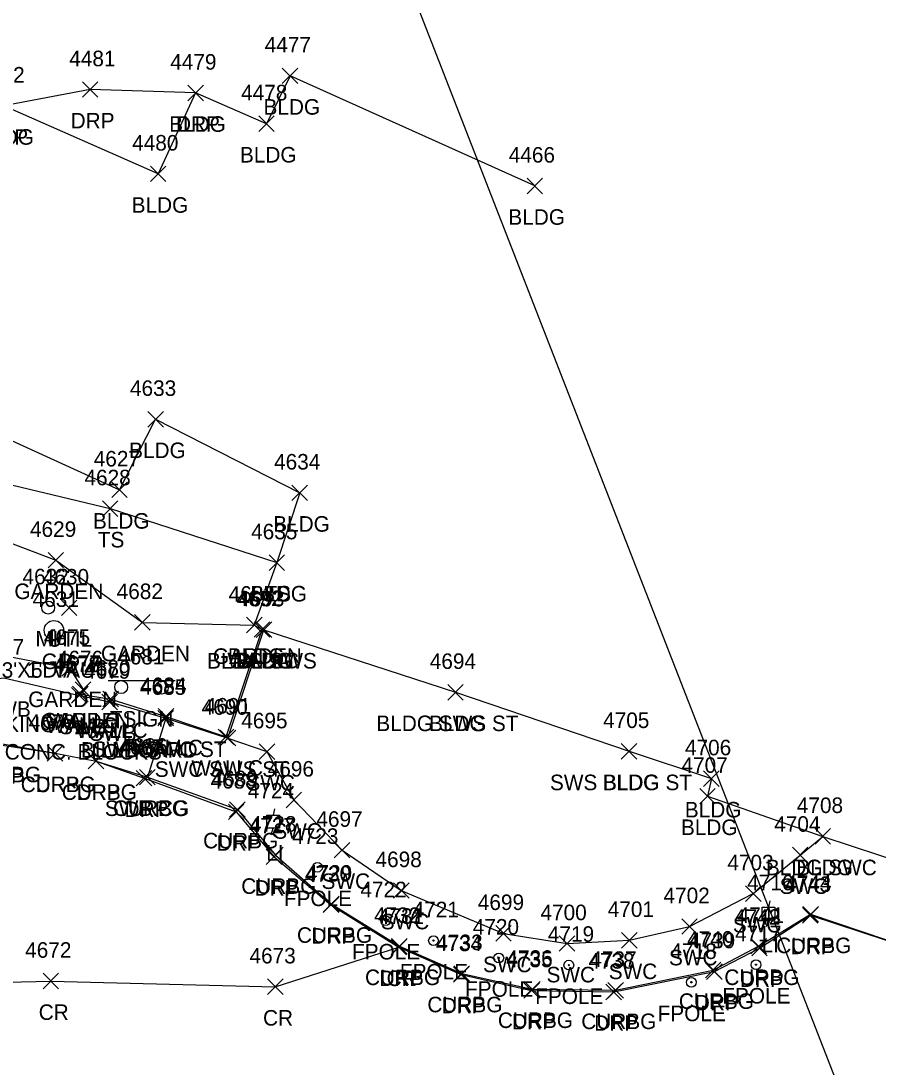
# Model space of a CAD drawing. Extents: x 49137 to 50946, y 9590 to 10709.
# Drawn here: x 50204 to 50314.2, y 10186.5 to 10321.1 of the extents above; entities that cross this region are included whole.
import ezdxf

# ---------------------------------------------------------------- set-up
doc = ezdxf.new("R2010")
doc.units = 0
for name, color, linetype in [('DCP', 7, 'Continuous'), ('L_A', 7, 'Continuous'), ('L_C', 7, 'Continuous'), ('L_I', 7, 'Continuous'), ('L_TIC', 7, 'Continuous'), ('LAPB', 7, 'Continuous'), ('LBC', 7, 'Continuous'), ('LELB', 7, 'Continuous'), ('LFP', 7, 'Continuous'), ('LW', 7, 'Continuous'), ('P_A', 7, 'Continuous'), ('P_I', 7, 'Continuous'), ('P_TIC', 7, 'Continuous'), ('PRC', 7, 'Continuous'), ('R_A', 7, 'Continuous'), ('R_I', 7, 'Continuous'), ('R_TIC', 7, 'Continuous'), ('RC', 7, 'Continuous'), ('RDP', 7, 'Continuous'), ('RGP', 7, 'Continuous'), ('RSW', 7, 'Continuous'), ('S_A', 7, 'Continuous'), ('S_C', 7, 'Continuous'), ('S_I', 7, 'Continuous'), ('SSGN', 7, 'Continuous'), ('U_A', 7, 'Continuous'), ('U_C', 7, 'Continuous'), ('U_I', 7, 'Continuous'), ('UDEFAULT', 7, 'Continuous'), ('ULP', 7, 'Continuous'), ('UUMH', 7, 'Continuous')]:
    doc.layers.add(name, color=color, linetype=linetype)

msp = doc.modelspace()

# ---------------------------------------------------------------- linework, layer by layer
at = {"layer": 'DCP'}
msp.add_lwpolyline([(49941.69, 9827.48), (50059.34, 9808.37), (50181.4, 9733.09), (50281.74, 9743.29), (50422.72, 9892.52), (50122.34, 10663.61), (50179.93, 10552.61), (50179.64, 10394.45), (50122.34, 10285.07), (50121.56, 10284.35)], dxfattribs=at)
at = {"layer": 'L_TIC'}
for points in [[(50237.6, 10313.07), (50239.6, 10315.07)], [(50239.6, 10313.07), (50237.6, 10315.07)], [(50225.45, 10310.86), (50227.45, 10312.86)], [(50227.45, 10310.86), (50225.45, 10312.86)], [(50234.57, 10306.91), (50236.57, 10308.91)], [(50236.57, 10306.91), (50234.57, 10308.91)], [(50220.64, 10300.45), (50222.64, 10302.45)], [(50222.64, 10300.45), (50220.64, 10302.45)], [(50269.1, 10298.9), (50271.1, 10300.9)], [(50271.1, 10298.9), (50269.1, 10300.9)], [(50220.31, 10268.88), (50222.31, 10270.88)], [(50222.31, 10268.88), (50220.31, 10270.88)], [(50215.66, 10259.8), (50217.66, 10261.8)], [(50217.66, 10259.8), (50215.66, 10261.8)], [(50238.85, 10259.41), (50240.85, 10261.41)], [(50240.85, 10259.41), (50238.85, 10261.41)], [(50214.46, 10257.38), (50216.46, 10259.38)], [(50216.46, 10257.38), (50214.46, 10259.38)], [(50207.47, 10250.74), (50209.47, 10252.74)], [(50209.47, 10250.74), (50207.47, 10252.74)], [(50235.9, 10250.43), (50237.9, 10252.43)], [(50237.9, 10250.43), (50235.9, 10252.43)], [(50235.9, 10250.43), (50237.9, 10252.43)], [(50237.9, 10250.43), (50235.9, 10252.43)], [(50218.61, 10242.74), (50220.61, 10244.74)], [(50220.61, 10242.74), (50218.61, 10244.74)], [(50233.01, 10242.4), (50235.01, 10244.4)], [(50235.01, 10242.4), (50233.01, 10244.4)], [(50233.01, 10242.4), (50235.01, 10244.4)], [(50235.01, 10242.4), (50233.01, 10244.4)], [(50234, 10241.83), (50236, 10243.83)], [(50236, 10241.83), (50234, 10243.83)], [(50234, 10241.83), (50236, 10243.83)], [(50236, 10241.83), (50234, 10243.83)], [(50234.24, 10241.8), (50236.24, 10243.8)], [(50236.24, 10241.8), (50234.24, 10243.8)], [(50209.25, 10236.84), (50211.25, 10238.84)], [(50211.25, 10236.84), (50209.25, 10238.84)], [(50210.97, 10234.09), (50212.97, 10236.09)], [(50212.97, 10234.09), (50210.97, 10236.09)], [(50210.97, 10234.09), (50212.97, 10236.09)], [(50212.97, 10234.09), (50210.97, 10236.09)], [(50258.89, 10233.75), (50260.89, 10235.75)], [(50260.89, 10233.75), (50258.89, 10235.75)], [(50210.63, 10233.52), (50212.63, 10235.52)], [(50212.63, 10233.52), (50210.63, 10235.52)], [(50214.53, 10232.88), (50216.53, 10234.88)], [(50216.53, 10232.88), (50214.53, 10234.88)], [(50221.64, 10230.64), (50223.64, 10232.64)], [(50223.64, 10230.64), (50221.64, 10232.64)], [(50229.37, 10228.01), (50231.37, 10230.01)], [(50231.37, 10228.01), (50229.37, 10230.01)], [(50281.22, 10226.15), (50283.22, 10228.15)], [(50283.22, 10226.15), (50281.22, 10228.15)], [(50291.8, 10222.64), (50293.8, 10224.64)], [(50293.8, 10222.64), (50291.8, 10224.64)], [(50291.3, 10220.38), (50293.3, 10222.38)], [(50293.3, 10220.38), (50291.3, 10222.38)], [(50306.14, 10215.21), (50308.14, 10217.21)], [(50308.14, 10215.21), (50306.14, 10217.21)]]:
    msp.add_lwpolyline(points, dxfattribs=at)
at = {"layer": 'LAPB'}
for points in [[(50157.96, 10267.97), (50152.3, 10249.84), (50148.96, 10238.47), (50151.49, 10231.52), (50159.69, 10232.28), (50178.06, 10237.47), (50196.39, 10240.52), (50210.25, 10237.84), (50211.97, 10235.09)], [(50157.96, 10267.97), (50167.36, 10269), (50188.37, 10259.39), (50208.47, 10251.74), (50219.61, 10243.74), (50234.01, 10243.4)]]:
    msp.add_lwpolyline(points, dxfattribs=at)
at = {"layer": 'LBC'}
for points in [[(50270.1, 10299.9), (50238.6, 10314.07), (50235.57, 10307.91), (50226.45, 10311.86), (50221.64, 10301.45), (50201.78, 10310.2), (50197.62, 10302.08), (50176.54, 10312.4), (50163.87, 10284.73), (50169.02, 10282.33), (50173.19, 10280.45), (50184.02, 10275.46), (50193.34, 10271.43), (50216.66, 10260.8), (50221.31, 10269.88), (50239.85, 10260.41), (50236.9, 10251.43), (50234.01, 10243.4), (50235, 10242.83), (50235.24, 10242.8), (50259.89, 10234.75)], [(50282.22, 10227.15), (50292.8, 10223.64), (50292.3, 10221.38), (50307.14, 10216.21), (50325.37, 10210.2), (50326.04, 10212.17), (50337.06, 10208.4)]]:
    msp.add_lwpolyline(points, dxfattribs=at)
at = {"layer": 'LELB'}
msp.add_lwpolyline([(50189.15, 10264.68), (50215.46, 10258.38), (50236.9, 10251.43)], dxfattribs=at)
at = {"layer": 'LFP'}
for centre, radius in [((50242.14, 10212.24), 0.625), ((50242.14, 10212.24), 0.0833), ((50250.91, 10205.37), 0.625), ((50250.91, 10205.37), 0.0833), ((50257.06, 10202.8), 0.625), ((50257.06, 10202.8), 0.0833), ((50265.46, 10200.57), 0.625), ((50265.46, 10200.57), 0.0833), ((50274.47, 10199.64), 0.625), ((50274.47, 10199.64), 0.0833), ((50298.54, 10199.7), 0.625), ((50298.54, 10199.7), 0.0833), ((50290.23, 10197.43), 0.625), ((50290.23, 10197.43), 0.0833)]:
    msp.add_circle(centre, radius, dxfattribs=at)
at = {"layer": 'LW'}
msp.add_lwpolyline([(50211.97, 10235.09), (50211.63, 10234.52), (50215.53, 10233.88), (50222.64, 10231.64), (50230.37, 10229.01), (50235, 10242.83)], dxfattribs=at)
at = {"layer": 'P_TIC'}
for points in [[(50251.6, 10200.95), (50253.6, 10202.95)], [(50253.6, 10200.95), (50251.6, 10202.95)], [(50206.83, 10196.59), (50208.83, 10198.59)], [(50208.83, 10196.59), (50206.83, 10198.59)], [(50235.7, 10195.86), (50237.7, 10197.86)], [(50237.7, 10195.86), (50235.7, 10197.86)]]:
    msp.add_lwpolyline(points, dxfattribs=at)
at = {"layer": 'PRC'}
msp.add_lwpolyline([(50141.03, 10194.61), (50160.28, 10196.49), (50207.83, 10197.59), (50236.7, 10196.86), (50252.6, 10201.95)], dxfattribs=at)
at = {"layer": 'R_TIC'}
for points in [[(50211.89, 10311.3), (50213.89, 10313.3)], [(50213.89, 10311.3), (50211.89, 10313.3)], [(50225.45, 10310.86), (50227.45, 10312.86)], [(50227.45, 10310.86), (50225.45, 10312.86)], [(50234.24, 10241.8), (50236.24, 10243.8)], [(50236.24, 10241.8), (50234.24, 10243.8)], [(50258.89, 10233.75), (50260.89, 10235.75)], [(50260.89, 10233.75), (50258.89, 10235.75)], [(50210.51, 10233.35), (50212.51, 10235.35)], [(50212.51, 10233.35), (50210.51, 10235.35)], [(50214.41, 10232.5), (50216.41, 10234.5)], [(50216.41, 10232.5), (50214.41, 10234.5)], [(50221.61, 10230.42), (50223.61, 10232.42)], [(50223.61, 10230.42), (50221.61, 10232.42)], [(50221.61, 10230.42), (50223.61, 10232.42)], [(50223.61, 10230.42), (50221.61, 10232.42)], [(50229.62, 10227.86), (50231.62, 10229.86)], [(50231.62, 10227.86), (50229.62, 10229.86)], [(50229.62, 10227.86), (50231.62, 10229.86)], [(50231.62, 10227.86), (50229.62, 10229.86)], [(50207.37, 10225.9), (50209.37, 10227.9)], [(50209.37, 10225.9), (50207.37, 10227.9)], [(50207.37, 10225.9), (50209.37, 10227.9)], [(50209.37, 10225.9), (50207.37, 10227.9)], [(50234.63, 10226.11), (50236.63, 10228.11)], [(50236.63, 10226.11), (50234.63, 10228.11)], [(50281.22, 10226.15), (50283.22, 10228.15)], [(50283.22, 10226.15), (50281.22, 10228.15)], [(50212.65, 10224.9), (50214.65, 10226.9)], [(50214.65, 10224.9), (50212.65, 10226.9)], [(50212.65, 10224.9), (50214.65, 10226.9)], [(50214.65, 10224.9), (50212.65, 10226.9)], [(50219.25, 10222.83), (50221.25, 10224.83)], [(50221.25, 10222.83), (50219.25, 10224.83)], [(50219.25, 10222.83), (50221.25, 10224.83)], [(50221.25, 10222.83), (50219.25, 10224.83)], [(50218.82, 10222.7), (50220.82, 10224.7)], [(50220.82, 10222.7), (50218.82, 10224.7)], [(50238.09, 10219.9), (50240.09, 10221.9)], [(50240.09, 10219.9), (50238.09, 10221.9)], [(50230.68, 10218.36), (50232.68, 10220.36)], [(50232.68, 10218.36), (50230.68, 10220.36)], [(50230.83, 10218.66), (50232.83, 10220.66)], [(50232.83, 10218.66), (50230.83, 10220.66)], [(50306.14, 10215.21), (50308.14, 10217.21)], [(50308.14, 10215.21), (50306.14, 10217.21)], [(50244.3, 10213.44), (50246.3, 10215.44)], [(50246.3, 10213.44), (50244.3, 10215.44)], [(50235.55, 10212.58), (50237.55, 10214.58)], [(50237.55, 10212.58), (50235.55, 10214.58)], [(50235.74, 10212.81), (50237.74, 10214.81)], [(50237.74, 10212.81), (50235.74, 10214.81)], [(50303.23, 10212.8), (50305.23, 10214.8)], [(50305.23, 10212.8), (50303.23, 10214.8)], [(50251.91, 10208.25), (50253.91, 10210.25)], [(50253.91, 10208.25), (50251.91, 10210.25)], [(50297.2, 10207.84), (50299.2, 10209.84)], [(50299.2, 10207.84), (50297.2, 10209.84)], [(50242.86, 10206.4), (50244.86, 10208.4)], [(50244.86, 10206.4), (50242.86, 10208.4)], [(50242.91, 10206.51), (50244.91, 10208.51)], [(50244.91, 10206.51), (50242.91, 10208.51)], [(50304.52, 10205.05), (50306.52, 10207.05)], [(50306.52, 10205.05), (50304.52, 10207.05)], [(50304.57, 10205.18), (50306.57, 10207.18)], [(50306.57, 10205.18), (50304.57, 10207.18)], [(50265.07, 10202.73), (50267.07, 10204.73)], [(50267.07, 10202.73), (50265.07, 10204.73)], [(50288.99, 10203.61), (50290.99, 10205.61)], [(50290.99, 10203.61), (50288.99, 10205.61)], [(50273.24, 10201.42), (50275.24, 10203.42)], [(50275.24, 10201.42), (50273.24, 10203.42)], [(50281.24, 10201.84), (50283.24, 10203.84)], [(50283.24, 10201.84), (50281.24, 10203.84)], [(50251.6, 10200.95), (50253.6, 10202.95)], [(50253.6, 10200.95), (50251.6, 10202.95)], [(50251.67, 10201.07), (50253.67, 10203.07)], [(50253.67, 10201.07), (50251.67, 10203.07)], [(50297.88, 10201.08), (50299.88, 10203.08)], [(50299.88, 10201.08), (50297.88, 10203.08)], [(50297.99, 10200.84), (50299.99, 10202.84)], [(50299.99, 10200.84), (50297.99, 10202.84)], [(50259.61, 10197.44), (50261.61, 10199.44)], [(50261.61, 10197.44), (50259.61, 10199.44)], [(50259.69, 10197.57), (50261.69, 10199.57)], [(50261.69, 10197.57), (50259.69, 10199.57)], [(50292.04, 10198.01), (50294.04, 10200.01)], [(50294.04, 10198.01), (50292.04, 10200.01)], [(50292.19, 10197.81), (50294.19, 10199.81)], [(50294.19, 10197.81), (50292.19, 10199.81)], [(50268.68, 10195.37), (50270.68, 10197.37)], [(50270.68, 10195.37), (50268.68, 10197.37)], [(50268.76, 10195.55), (50270.76, 10197.55)], [(50270.76, 10195.55), (50268.76, 10197.55)], [(50279.24, 10195.19), (50281.24, 10197.19)], [(50281.24, 10195.19), (50279.24, 10197.19)], [(50279.49, 10195.41), (50281.49, 10197.41)], [(50281.49, 10195.41), (50279.49, 10197.41)]]:
    msp.add_lwpolyline(points, dxfattribs=at)
at = {"layer": 'RC'}
for points in [[(50134.83, 10210.94), (50148.5, 10215.78), (50176.2, 10225.13), (50201.35, 10228.17), (50208.37, 10226.9)], [(50213.65, 10225.9), (50220.25, 10223.83), (50231.83, 10219.66), (50236.74, 10213.81), (50243.91, 10207.51), (50252.67, 10202.07), (50260.69, 10198.57), (50269.76, 10196.55), (50280.49, 10196.41), (50293.04, 10199.01), (50298.88, 10202.08), (50305.57, 10206.18), (50321.8, 10200.71), (50345.08, 10192.8), (50360.62, 10187.73)]]:
    msp.add_lwpolyline(points, dxfattribs=at)
at = {"layer": 'RDP'}
for points in [[(50226.45, 10311.86), (50212.89, 10312.3), (50201.78, 10310.2), (50176.54, 10312.4), (50172.29, 10313.45), (50170, 10312.64), (50168.76, 10311.3), (50158.71, 10286.84), (50151.3, 10264.14), (50142.8, 10239.53), (50142.92, 10234.15), (50145.3, 10229.21), (50150.3, 10224.7), (50136.97, 10219.75), (50131.76, 10217.66), (50126, 10213.97)], [(50134.83, 10210.94), (50148.54, 10215.59), (50176.21, 10224.92), (50201.3, 10228), (50208.37, 10226.9), (50213.65, 10225.9), (50219.82, 10223.7), (50231.68, 10219.36), (50236.55, 10213.58), (50243.86, 10207.4), (50252.6, 10201.95), (50260.61, 10198.44), (50269.68, 10196.37), (50280.24, 10196.19), (50293.19, 10198.81), (50298.99, 10201.84), (50305.52, 10206.05), (50321.81, 10200.69), (50344.92, 10192.72), (50360.45, 10187.55)]]:
    msp.add_lwpolyline(points, dxfattribs=at)
at = {"layer": 'RGP'}
msp.add_line((50208.23, 10242.73), (50208.23, 10242.73), dxfattribs=at)
for radius in [1.25, 0.0833]:
    msp.add_circle((50208.23, 10242.73), radius, dxfattribs=at)
at = {"layer": 'RSW'}
for points in [[(50230.62, 10228.86), (50235.24, 10242.8)], [(50150.3, 10224.7), (50174.04, 10232.99), (50201.8, 10236.59), (50211.51, 10234.35), (50215.41, 10233.5), (50222.61, 10231.42), (50220.25, 10223.83)], [(50259.89, 10234.75), (50282.22, 10227.15)], [(50222.61, 10231.42), (50230.62, 10228.86), (50235.63, 10227.11), (50239.09, 10220.9), (50245.3, 10214.44), (50252.91, 10209.25), (50266.07, 10203.73), (50274.24, 10202.42), (50282.24, 10202.84), (50289.99, 10204.61), (50298.2, 10208.84), (50304.23, 10213.8), (50307.14, 10216.21), (50325.37, 10210.2), (50323.8, 10206.38), (50321.8, 10200.71)]]:
    msp.add_lwpolyline(points, dxfattribs=at)
at = {"layer": 'SSGN'}
for p, q in [((50215.22, 10236.26), (50223.82, 10236.26)), ((50219.24, 10235.35), (50219.24, 10235.35))]:
    msp.add_line(p, q, dxfattribs=at)
for centre in [(50216.88, 10235.42), (50222.1, 10235.35)]:
    msp.add_circle(centre, 0.833, dxfattribs=at)
at = {"layer": 'UDEFAULT'}
for points in [[(50209.19, 10244.61), (50211.19, 10246.61)], [(50211.19, 10244.61), (50209.19, 10246.61)]]:
    msp.add_lwpolyline(points, dxfattribs=at)
at = {"layer": 'ULP'}
for p, q in [((50236.6, 10219.76), (50236.43, 10218.92)), ((50235.6, 10217.26), (50235.6, 10218.92)), ((50235.6, 10218.92), (50237.26, 10218.92)), ((50236.43, 10218.09), (50236.43, 10218.09)), ((50237.26, 10218.92), (50237.26, 10217.26)), ((50237.26, 10217.26), (50235.6, 10217.26)), ((50236.18, 10216.42), (50236.43, 10217.26)), ((50300.32, 10207.93), (50300.16, 10207.1)), ((50299.32, 10205.43), (50299.32, 10207.1)), ((50299.32, 10207.1), (50300.99, 10207.1)), ((50300.16, 10206.27), (50300.16, 10206.27)), ((50300.99, 10207.1), (50300.99, 10205.43)), ((50300.99, 10205.43), (50299.32, 10205.43)), ((50299.91, 10204.6), (50300.16, 10205.43))]:
    msp.add_line(p, q, dxfattribs=at)
at = {"layer": 'UUMH'}
for p, q in [((50207.49, 10245.64), (50207.49, 10245.64)), ((50208.33, 10245.64), (50208.33, 10245.64))]:
    msp.add_line(p, q, dxfattribs=at)
msp.add_circle((50207.49, 10245.64), 0.833, dxfattribs=at)

# ---------------------------------------------------------------- texts
at = {"layer": 'L_A'}
for s, p in [('BLDG', (50235.19, 10309.07)), ('BLDG', (50223.05, 10306.86)), ('BLDG', (50198.37, 10305.2)), ('BLDG', (50232.16, 10302.91)), ('BLDG', (50218.23, 10296.45)), ('BLDG', (50266.69, 10294.9)), ('BLDG', (50217.9, 10264.88)), ('BLDG', (50213.25, 10255.8)), ('BLDG', (50236.44, 10255.41)), ('TS', (50213.87, 10253.38)), ('GARDEN', (50203.14, 10246.74)), ('BLDG', (50233.5, 10246.43)), ('TS', (50235.31, 10246.43)), ('GARDEN', (50214.28, 10238.74)), ('GARDEN', (50228.68, 10238.4)), ('WALLC', (50230.54, 10237.83)), ('BLDG', (50230.6, 10238.4)), ('BLDG', (50231.59, 10237.83)), ('BLDG', (50231.83, 10237.8)), ('GARDEN', (50204.92, 10232.84)), ('GARDEN', (50206.63, 10230.09)), ('WALLC', (50207.16, 10229.52)), ('WALLC', (50207.5, 10230.09)), ('BLDG', (50256.48, 10229.75)), ('WALLC', (50211.06, 10228.88)), ('WALLC', (50218.18, 10226.64)), ('WALLC', (50225.91, 10224.01)), ('BLDG', (50278.81, 10222.15)), ('BLDG', (50289.39, 10218.64)), ('BLDG', (50288.89, 10216.38)), ('BLDG', (50303.73, 10211.21)), ('FPOLE', (50237.81, 10207.24)), ('FPOLE', (50246.58, 10200.37)), ('FPOLE', (50252.73, 10197.8)), ('FPOLE', (50261.12, 10195.57)), ('FPOLE', (50270.14, 10194.64)), ('FPOLE', (50294.21, 10194.7)), ('FPOLE', (50285.89, 10192.43))]:
    msp.add_text(s, height=2, dxfattribs=at).set_placement(p)
at = {"layer": 'L_C'}
msp.add_text('CONC. BLOCKS', height=2, dxfattribs=at).set_placement((50201.9, 10226.09))
at = {"layer": 'L_I'}
for s, p in [('4477', (50235.34, 10317.07)), ('4479', (50223.19, 10314.86)), ('4482', (50198.52, 10313.2)), ('4478', (50232.31, 10310.91)), ('4480', (50218.29, 10304.45)), ('4466', (50266.74, 10302.9)), ('4633', (50218.01, 10272.88)), ('4627', (50213.35, 10263.8)), ('4634', (50236.55, 10263.41)), ('4628', (50212.16, 10261.38)), ('4629', (50205.15, 10254.74)), ('4635', (50233.6, 10254.43)), ('4635', (50233.6, 10254.43)), ('4682', (50216.3, 10246.74)), ('4683', (50230.7, 10246.4)), ('4683', (50230.7, 10246.4)), ('4692', (50231.7, 10245.83)), ('4692', (50231.7, 10245.83)), ('4693', (50231.93, 10245.8)), ('4675', (50206.94, 10240.84)), ('4676', (50208.6, 10238.09)), ('4676', (50208.6, 10238.09)), ('4694', (50256.58, 10237.75)), ('4677', (50208.32, 10237.52)), ('4680', (50212.13, 10236.88)), ('4684', (50219.33, 10234.64)), ('4691', (50227.63, 10232.01)), ('4705', (50278.88, 10230.15)), ('4706', (50289.41, 10226.64)), ('4707', (50288.96, 10224.38)), ('4708', (50303.8, 10219.21)), ('4723', (50238.88, 10215.24)), ('4722', (50247.65, 10208.37)), ('4721', (50254.37, 10205.8)), ('4720', (50262.11, 10203.57)), ('4719', (50271.77, 10202.64)), ('4717', (50295.85, 10202.7)), ('4718', (50287.53, 10200.43))]:
    msp.add_text(s, height=2, dxfattribs=at).set_placement(p)
at = {"layer": 'P_A'}
for p in [(50251.03, 10196.95), (50206.27, 10192.59), (50235.13, 10191.86)]:
    msp.add_text('CR', height=2, dxfattribs=at).set_placement(p)
at = {"layer": 'P_I'}
for s, p in [('4731', (50249.91, 10204.95)), ('4672', (50204.53, 10200.59)), ('4673', (50233.39, 10199.86))]:
    msp.add_text(s, height=2, dxfattribs=at).set_placement(p)
at = {"layer": 'R_A'}
for s, p in [('DRP', (50210.38, 10307.3)), ('DRP', (50223.94, 10306.86)), ('DRP', (50199.27, 10305.2)), ('GP', (50206.66, 10237.73)), ('BLDG SWS', (50227.93, 10237.8)), ('SWB', (50199.16, 10231.59)), ('BLDG SWS ST', (50249.71, 10229.75)), ('SWB', (50208.88, 10229.35)), ('SWB', (50212.77, 10228.5)), ('SWB SWC ST', (50213.2, 10226.42)), ('SWB SWC ST', (50213.2, 10226.42)), ('CURBG', (50196.93, 10223.17)), ('DRP', (50198.79, 10223)), ('SWC SWS ST', (50221.21, 10223.86)), ('SWC SWS ST', (50221.21, 10223.86)), ('CURBG', (50203.96, 10221.9)), ('DRP', (50205.86, 10221.9)), ('SWC', (50232.99, 10222.11)), ('SWS BLDG ST', (50272.04, 10222.15)), ('CURBG', (50209.24, 10220.9)), ('DRP', (50211.14, 10220.9)), ('SWB CG', (50214.78, 10218.83)), ('CURBG', (50215.83, 10218.83)), ('DRP', (50217.31, 10218.7)), ('SWC', (50236.45, 10215.9)), ('CURBG', (50227.42, 10214.66)), ('DRP', (50229.17, 10214.36)), ('BLDG SWC', (50299.82, 10211.21)), ('SWC', (50242.66, 10209.44)), ('CURBG', (50232.33, 10208.81)), ('DRP', (50234.04, 10208.58)), ('SWC', (50301.59, 10208.8)), ('SWC', (50250.27, 10204.25)), ('SWC', (50295.57, 10203.84)), ('CURBG', (50239.5, 10202.51)), ('DRP', (50241.35, 10202.4)), ('CURBG', (50301.15, 10201.18)), ('DRP', (50303.01, 10201.05)), ('SWC', (50263.43, 10198.73)), ('SWC', (50287.35, 10199.61)), ('SWC', (50271.6, 10197.42)), ('SWC', (50279.6, 10197.84)), ('CURBG', (50248.25, 10197.07)), ('DRP', (50250.09, 10196.95)), ('CURBG', (50294.47, 10197.08)), ('DRP', (50296.48, 10196.84)), ('CURBG', (50256.27, 10193.57)), ('DRP', (50258.1, 10193.44)), ('CURBG', (50288.62, 10194.01)), ('DRP', (50290.68, 10193.81)), ('CURBG', (50265.34, 10191.55)), ('DRP', (50267.17, 10191.37)), ('CURBG', (50276.07, 10191.41)), ('DRP', (50277.73, 10191.19))]:
    msp.add_text(s, height=2, dxfattribs=at).set_placement(p)
at = {"layer": 'R_I'}
for s, p in [('4481', (50210.2, 10315.3)), ('4479', (50223.19, 10314.86)), ('4482', (50198.52, 10313.2)), ('4631', (50205.49, 10245.73)), ('4693', (50231.93, 10245.8)), ('4667', (50198.45, 10239.59)), ('4694', (50256.58, 10237.75)), ('4678', (50208.21, 10237.35)), ('4679', (50212.1, 10236.5)), ('4685', (50219.3, 10234.42)), ('4685', (50219.3, 10234.42)), ('4690', (50227.23, 10231.86)), ('4690', (50227.23, 10231.86)), ('4670', (50204.98, 10229.9)), ('4670', (50204.98, 10229.9)), ('4695', (50232.33, 10230.11)), ('4705', (50278.88, 10230.15)), ('4671', (50210.91, 10228.9)), ('4671', (50210.91, 10228.9)), ('4686', (50216.89, 10226.83)), ('4686', (50216.89, 10226.83)), ('4687', (50216.51, 10226.7)), ('4696', (50235.73, 10223.9)), ('4688', (50228.37, 10222.36)), ('4689', (50228.52, 10222.66)), ('4708', (50303.8, 10219.21)), ('4697', (50241.99, 10217.44)), ('4727', (50233.29, 10216.58)), ('4728', (50233.48, 10216.81)), ('4704', (50300.89, 10216.8)), ('4698', (50249.6, 10212.25)), ('4703', (50294.86, 10211.84)), ('4730', (50240.51, 10210.4)), ('4729', (50240.65, 10210.51)), ('4743', (50302.26, 10209.05)), ('4744', (50302.31, 10209.18)), ('4699', (50262.76, 10206.73)), ('4702', (50286.65, 10207.61)), ('4700', (50270.82, 10205.42)), ('4701', (50279.47, 10205.84)), ('4732', (50249.41, 10205.07)), ('4731', (50249.91, 10204.95)), ('4742', (50295.73, 10204.84)), ('4741', (50296.19, 10205.08)), ('4734', (50257.35, 10201.44)), ('4733', (50257.43, 10201.57)), ('4740', (50289.69, 10202.01)), ('4739', (50289.92, 10201.81)), ('4735', (50266.42, 10199.37)), ('4736', (50266.45, 10199.55)), ('4738', (50276.98, 10199.19)), ('4737', (50277.23, 10199.41))]:
    msp.add_text(s, height=2, dxfattribs=at).set_placement(p)
at = {"layer": 'S_A'}
msp.add_text('TSIGN', height=2, dxfattribs=at).set_placement((50215.42, 10230.33))
at = {"layer": 'S_C'}
for s, p in [('HANDICAP PARKING', (50181.9, 10229.63)), ('BILLBOARD', (50211.7, 10226.33))]:
    msp.add_text(s, height=2, dxfattribs=at).set_placement(p)
at = {"layer": 'S_I'}
msp.add_text('4681', height=2, dxfattribs=at).set_placement((50216.5, 10238.33))
at = {"layer": 'U_A'}
for s, p in [('MH', (50205.85, 10240.64)), ('UTIL', (50207.35, 10240.61)), ('LI', (50235.53, 10213.09)), ('LI', (50299.26, 10201.27))]:
    msp.add_text(s, height=2, dxfattribs=at).set_placement(p)
at = {"layer": 'U_C'}
for s, p in [("3'X5' VAUTL", (50201.51, 10236.61)), ("1'DIA", (50204.74, 10236.64))]:
    msp.add_text(s, height=2, dxfattribs=at).set_placement(p)
at = {"layer": 'U_I'}
for s, p in [('4632', (50204.19, 10248.64)), ('4630', (50206.8, 10248.61)), ('4724', (50233.17, 10221.09)), ('4716', (50297.41, 10209.27))]:
    msp.add_text(s, height=2, dxfattribs=at).set_placement(p)

doc.saveas('drawing.dxf')
